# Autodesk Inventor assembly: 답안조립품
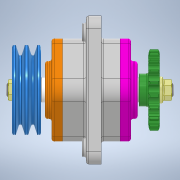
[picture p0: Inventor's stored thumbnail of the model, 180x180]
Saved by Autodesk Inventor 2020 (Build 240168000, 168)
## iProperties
Created: 2021-07
Part Number: 답안조립품
Document SubType Name: Assembly
Designer: Owner
Author: Owner
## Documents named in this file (16)
- C:\Users\Owner\Desktop\710707V1003\710707V1003\답안조립품.iam
- C:\Users\Owner\Desktop\710707V1003\710707V1003\본체.ipt
- C:\Users\Owner\Desktop\710707V1003\710707V1003\M16 너트.ipt
- C:\Users\Owner\Desktop\710707V1003\710707V1003\V-벨트풀리.ipt
- C:\Users\Owner\Desktop\710707V1003\710707V1003\멈춤나사 M4.ipt
- C:\Users\Owner\Desktop\710707V1003\710707V1003\베어링 6206.ipt
- C:\Users\Owner\Desktop\710707V1003\710707V1003\볼트 M6.ipt
- C:\Users\Owner\Desktop\710707V1003\710707V1003\부시.ipt
- C:\Users\Owner\Desktop\710707V1003\710707V1003\오일실 30x42x8.ipt
- C:\Users\Owner\Desktop\710707V1003\710707V1003\오일실 30x45x8.ipt
- C:\Users\Owner\Desktop\710707V1003\710707V1003\체인 스프로킷.ipt
- C:\Users\Owner\Desktop\710707V1003\710707V1003\축.ipt
- C:\Users\Owner\Desktop\710707V1003\710707V1003\커버A.ipt
- C:\Users\Owner\Desktop\710707V1003\710707V1003\커버B.ipt
- C:\Users\Owner\Desktop\710707V1003\710707V1003\키 6x6x18.ipt
- C:\Users\Owner\Desktop\710707V1003\710707V1003\키 6x6x20.ipt
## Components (3 placed, 2 different names)
1. M16 너트:1
2. V-벨트풀리:1 — 각도:2
3. M16 너트:2
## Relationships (1: Angle 1)
- 각도:2 [Angle]: V-벨트풀리:1
